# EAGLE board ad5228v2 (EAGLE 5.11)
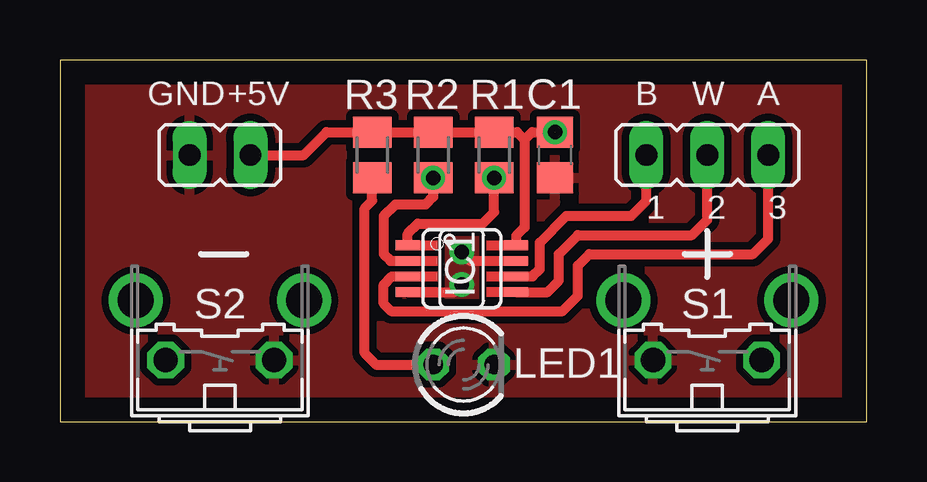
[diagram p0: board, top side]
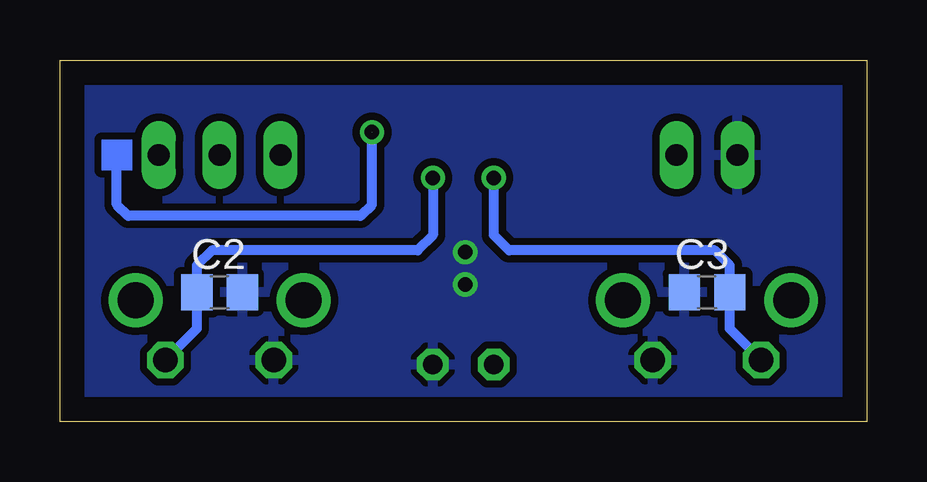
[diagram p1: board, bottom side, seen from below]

Size 33.64 x 15.07 mm. Coordinates in mm from the lower left corner, seen from the top.
Outline: 0,0 33.64,0 33.64,15.07 0,15.07 0,0
Copper layers (1*16): Top 0.035mm / dielectric 1.5mm / Bottom 0.035mm
Design rules "default": minimum track width 10mil, minimum drill 24mil, track to track 8mil, track to pad 8mil, pad to pad 8mil, via to via 8mil, smd to smd 8mil, copper to edge 40mil, drill to drill 8mil, minimum pad ring 10mil, minimum via ring 8mil, stop-mask expansion 4mil, vias tented up to drill 0mil, thermal gap 10mil

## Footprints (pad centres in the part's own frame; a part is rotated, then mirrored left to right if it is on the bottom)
C0805 = smd 1.3 x 1.5: 1 -0.95,0; 2 0.95,0
MSOP08 = smd 0.4 x 1: 1 -0.976,-2.263; 2 -0.326,-2.263; 3 0.324,-2.263; 4 0.974,-2.263; 5 0.974,2.262; 6 0.324,2.262; 7 -0.326,2.262; 8 -0.976,2.262
JP1 = drill 0.914 long: 1 0,-1.27; 2 0,1.27
JP2 = drill 0.914 long: 1 -2.54,0; 2 0,0; 3 2.54,0
LED3MM = drill 0.813 octagon: A -1.27,0; K 1.27,0
M0805 = smd 1.3 x 1.6: 1 -0.95,0; 2 0.95,0
B3F-31XX = drill 1.016 octagon: 1 -2.261,-1.245; 2 2.261,-1.245 | drill 1.499 pad 2.159 round: 3 -3.505,1.245; 4 3.505,1.245

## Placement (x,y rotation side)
C1  [C0805]  20.64,11.11 270 top
C2  [C0805]  26.99,5.4 180 bottom
C3  [C0805]  6.67,5.4 180 bottom
IC1  AD822RM  [MSOP08]  16.76,6.38 270 top
JP1  [JP1]  6.67,11.11 270 top
JP2  [JP2]  26.99,11.11 0 top
LED1  [LED3MM]  16.83,2.38 0 top
R1  [M0805]  18.1,11.11 90 top
R2  [M0805]  15.56,11.11 90 top
R3  [M0805]  13.02,11.11 90 top
S1  [B3F-31XX]  26.99,3.81 0 top
S2  [B3F-31XX]  6.67,3.81 0 top

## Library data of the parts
C1-C3 R1-R3 = rcl
IC1 = analog-devices; MPN: AD822ARMZ-R2; OC_FARNELL: 1827360; OC_NEWARK: 19M8890
JP1 JP2 = jumper
LED1 = led
S1 S2 = switch-omron; MPN: B3F-3100; OC_FARNELL: 959704; OC_NEWARK: 36M3582

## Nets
GND: C1.2 C2.1 C3.2 IC1.4 IC1.7 JP1.1 LED1.K S1.1 S2.2
N$2: IC1.5 JP2.2
N$3: LED1.A R3.1
N$4: C3.1 IC1.2 R2.1 S2.1
N$5: C2.2 IC1.1 R1.1 S1.2
N$7: C1.1 IC1.8 JP1.2 R1.2 R2.2 R3.2
N$8: IC1.3 JP2.3
N$9: IC1.6 JP2.1

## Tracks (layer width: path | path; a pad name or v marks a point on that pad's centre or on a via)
GND  (via drill 0.6)
  Top 0.406: IC1.4 16.43,5.4 v16.75,5.71 | IC1.7 17.11,6.7 v16.75,7.06
  pour Bottom (isolate 0.305): 0,15.08 33.66,15.08 33.66,0 0,0
  pour Top (isolate 0.305): 0,15.08 0,0 33.66,0 33.66,15.08
N$1
  Top 0: 14.27,7.55
N$2
  Top 0.406: IC1.5 20.32,5.4 20.8,5.87 20.8,6.98 21.59,7.78 26.35,7.78 26.99,8.41 JP2.2 | JP2.2
N$3
  Top 0.406: LED1.A 13.18,2.38 12.7,2.86 12.7,8.89 13.02,9.21 R3.1
N$4  (via drill 0.6)
  Top 0.406: IC1.2 13.78,6.7 13.49,6.98 13.49,8.57 13.97,9.05 15.24,9.05 15.56,9.37 R2.1 | R2.1 | R2.1
  Bottom 0.406: S2.1 5.72,3.88 C3.1 5.72,6.51 6.35,7.14 14.92,7.14 15.56,7.78 R2.1
  other vias: 15.56,10.16
N$5  (via drill 0.6)
  Top 0.406: IC1.1 14.49,7.83 14.92,8.25 17.62,8.25 18.1,8.73 R1.1
  Bottom 0.406: S1.2 27.94,3.88 C2.2 27.94,6.51 27.31,7.14 18.73,7.14 18.1,7.78 R1.1
  other vias: 18.1,10.16
N$7  (via drill 0.6)  (1 unrouted)
  Top 0.406: JP1.2 | JP1.2 10.16,11.11 11.11,12.06 R3.2 R2.2 R1.2 19.05,12.06 19.37,11.75 | C1.1 19.68,12.06 19.37,11.75 | IC1.8 19.02,7.75 19.37,8.1 19.37,11.75 | C1.1 20.64,12.22
  Bottom 0.406: 31.27,11.11 31.27,9.05 30.8,8.57 21.11,8.57 20.64,9.05 C1.1
  other vias: 20.64,12.06
N$8
  Top 0.406: JP2.3 | JP2.3 29.53,7.62 28.89,6.98 22.07,6.98 21.59,6.51 21.59,5.24 20.96,4.6 13.81,4.6 13.49,4.92 13.49,5.71 13.83,6.05 IC1.3
N$9
  Top 0.406: IC1.6 19.7,6.05 20,6.35 20,7.46 21.11,8.57 23.81,8.57 24.45,9.21 JP2.1 | JP2.1
(copper drawn outside any net)
  shapes: Bottom area x1, Top area x8

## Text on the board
tPlace: GND | +5V | B | W | A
